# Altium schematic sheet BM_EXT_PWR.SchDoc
size A4; SheetNumber: 6; SheetTotal: 15
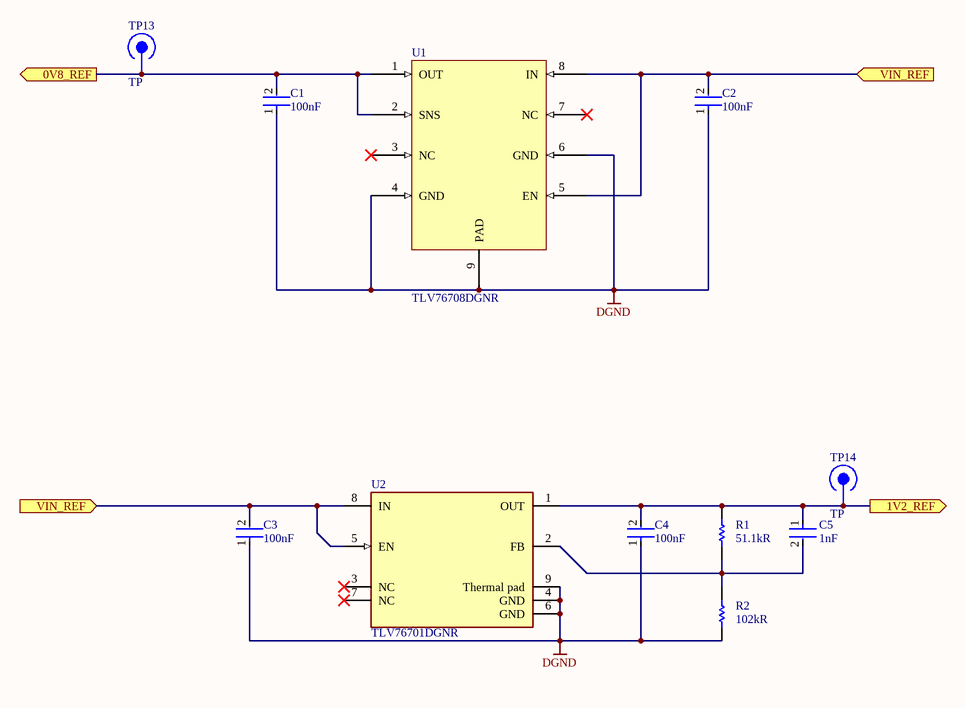
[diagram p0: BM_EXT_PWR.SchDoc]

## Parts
C1  value 100nF  [FP-CC0402-IPC_B]  (hidden comment: CC0402KRX7R9BB104)
C2  value 100nF  [FP-CC0402-IPC_B]  (hidden comment: CC0402KRX7R9BB104)
C3  value 100nF  [FP-CC0402-IPC_B]  (hidden comment: CC0402KRX7R9BB104)
C4  value 100nF  [FP-CC0402-IPC_B]  (hidden comment: CC0402KRX7R9BB104)
C5  value 1nF  [FP-CC0805-0_85-MFG]  (hidden comment: CC0805KRX7R9BB102)
R1  value 51.1kR  [RESC1005X40X25LL10T10]  (hidden comment: RK73H1ETTP5112F)
R2  value 102kR  [RESC1005X40X25LL10T10]  (hidden comment: RK73H1ETTP1023F)
TP13  TP  [TP-Footprint-1]
TP14  TP  [TP-Footprint-1]
U1  TLV76708DGNR  [TLV76708DGNR-Footprint-1]
U2  TLV76701DGNR  [FP-DGN0008G-MFG]

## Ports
0V8_REF (out), 1V2_REF (out), VIN_REF (in)

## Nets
DGND: C1.1 C2.1 C3.1 C4.1 R2.1 U1.4(GND) U1.6(GND) U1.9(PAD) U2.4(GND) U2.6(GND) U2.9(Thermal_pad)
0V8_REF: C1.2 TP13.1 U1.1(OUT) U1.2(SNS) ; port 0V8_REF
1V2_REF: C4.2 C5.1 R1.2 TP14.1 U2.1(OUT) ; port 1V2_REF
VIN_REF: C2.2 C3.2 U1.5(EN) U1.8(IN) U2.5(EN) U2.8(IN) ; port VIN_REF
NetC5_2: C5.2 R1.1 R2.2 U2.2(FB)

Not connected (* = marked no-connect by the designer): U1 3(NC)* 7(NC)*; U2 3(NC)* 7(NC)*

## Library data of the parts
C1-C4 = CMP-x00152-1: Ceramic Capacitor, Multilayer, Ceramic, 50V, 10% +Tol, 10% -Tol, X7R, 15% TC, 0.1uF, Surface Mount, 0402
C5 = CMP-x00143-1: Ceramic Capacitor, Multilayer, Ceramic, 50V, 10% +Tol, 10% -Tol, X7R, 15% TC, 0.001uF, Surface Mount, 0805
R1 = CMP-x00159-1: Fixed Resistor, Metal Glaze/thick Film, 0.1W, 51100ohm, 75V, 1% +/-Tol, 100ppm/Cel, Surface Mount, 0402
R2 = CMP-x00160-1: Fixed Resistor, Metal Glaze/thick Film, 0.1W, 102000ohm, 75V, 1% +/-Tol, 100ppm/Cel, Surface Mount, 0402
TP13 TP14 = CMP-001-0086-3: digital shovel test point
U1 = CMP-x00161-1: Adjustable- and fixed-output, 1-A, 16-V, positive-voltage low-dropout (LDO) linear regulator 8-HVSSOP -40 to 125
U2 = CMP-x00158-1: Adjustable Positive Standard Regulator, 0.8V Min, 13.6V Max, PDSO8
